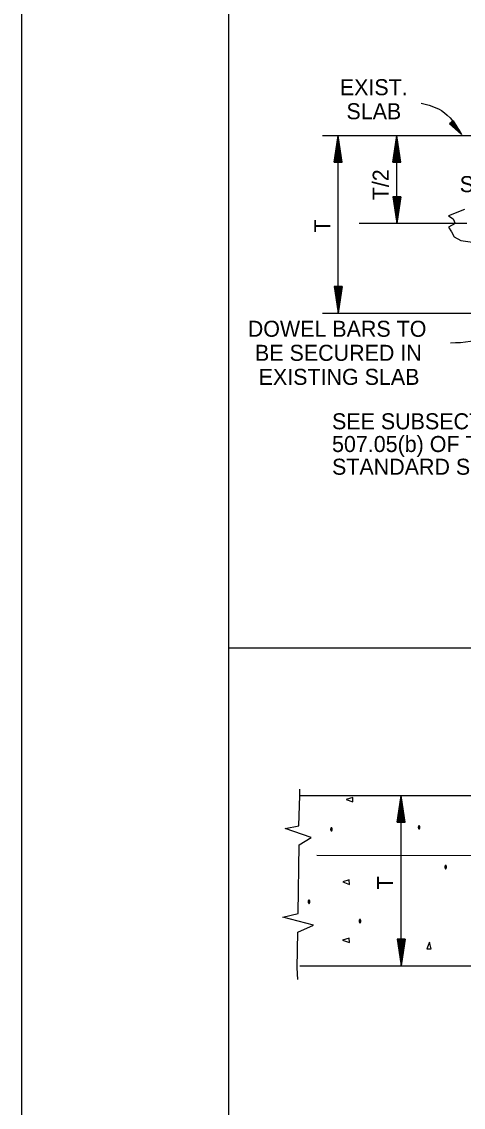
# Model space of a CAD drawing. Extents: x 1375738 to 1375905, y 380661 to 380875.
# Drawn here: x 1375738.22 to 1375751.44, y 380817.52 to 380850.01 of the extents above; entities that cross this region are included whole.
import ezdxf

# ---------------------------------------------------------------- set-up
doc = ezdxf.new("R2010")
doc.units = 0
for name, color, linetype in [('R_Border', 7, 'Continuous'), ('R_Draft', 7, 'Continuous'), ('R_No Plot', 7, 'Continuous')]:
    doc.layers.add(name, color=color, linetype=linetype)

msp = doc.modelspace()

# ---------------------------------------------------------------- linework, layer by layer
at = {"layer": 'R_Border'}
for p, q in [((1375744.419, 380770.053), (1375744.419, 380872.783)), ((1375744.419, 380831.274), (1375786.095, 380831.274))]:
    msp.add_line(p, q, dxfattribs=at)
at = {"layer": 'R_Draft'}
for p, q in [((1375751.135, 380847.052), (1375751.025, 380846.96)), ((1375751.025, 380846.96), (1375751.39, 380846.64)), ((1375751.034, 380846.967), (1375751.338, 380846.701)), ((1375751.043, 380846.975), (1375751.285, 380846.764)), ((1375751.053, 380846.983), (1375751.233, 380846.825)), ((1375751.062, 380846.991), (1375751.181, 380846.887)), ((1375751.071, 380846.999), (1375751.129, 380846.948)), ((1375751.088, 380847.013), (1375751.129, 380846.948)), ((1375751.097, 380847.021), (1375751.181, 380846.887)), ((1375751.107, 380847.029), (1375751.233, 380846.825)), ((1375751.116, 380847.037), (1375751.285, 380846.764)), ((1375751.125, 380847.045), (1375751.338, 380846.701)), ((1375751.135, 380847.052), (1375751.39, 380846.64)), ((1375747.225, 380846.607), (1375756.842, 380846.602)), ((1375747.574, 380845.806), (1375747.694, 380846.606)), ((1375747.594, 380845.806), (1375747.694, 380846.472)), ((1375747.694, 380841.293), (1375747.694, 380846.606)), ((1375747.814, 380845.806), (1375747.694, 380846.606)), ((1375747.794, 380845.806), (1375747.694, 380846.472)), ((1375749.326, 380845.806), (1375749.446, 380846.606)), ((1375749.346, 380845.806), (1375749.446, 380846.472)), ((1375749.446, 380843.972), (1375749.446, 380846.606)), ((1375749.566, 380845.806), (1375749.446, 380846.606)), ((1375749.546, 380845.806), (1375749.446, 380846.472)), ((1375747.615, 380845.806), (1375747.694, 380846.335)), ((1375747.635, 380845.806), (1375747.694, 380846.202)), ((1375747.774, 380845.806), (1375747.694, 380846.335)), ((1375747.754, 380845.806), (1375747.694, 380846.202)), ((1375749.367, 380845.806), (1375749.446, 380846.335)), ((1375749.387, 380845.806), (1375749.446, 380846.202)), ((1375749.526, 380845.806), (1375749.446, 380846.335)), ((1375749.506, 380845.806), (1375749.446, 380846.202)), ((1375747.655, 380845.806), (1375747.694, 380846.066)), ((1375747.675, 380845.806), (1375747.694, 380845.932)), ((1375747.733, 380845.806), (1375747.694, 380846.066)), ((1375747.713, 380845.806), (1375747.694, 380845.932)), ((1375749.407, 380845.806), (1375749.446, 380846.066)), ((1375749.427, 380845.806), (1375749.446, 380845.932)), ((1375749.485, 380845.806), (1375749.446, 380846.066)), ((1375749.465, 380845.806), (1375749.446, 380845.932)), ((1375747.574, 380845.806), (1375747.814, 380845.806)), ((1375749.326, 380845.806), (1375749.566, 380845.806)), ((1375749.326, 380844.772), (1375749.446, 380843.972)), ((1375749.566, 380844.772), (1375749.326, 380844.772)), ((1375749.346, 380844.772), (1375749.446, 380844.105)), ((1375749.367, 380844.772), (1375749.446, 380844.243)), ((1375749.387, 380844.772), (1375749.446, 380844.376)), ((1375749.407, 380844.772), (1375749.446, 380844.512)), ((1375749.427, 380844.772), (1375749.446, 380844.645)), ((1375749.566, 380844.772), (1375749.446, 380843.972)), ((1375749.485, 380844.772), (1375749.446, 380844.512)), ((1375749.526, 380844.772), (1375749.446, 380844.243)), ((1375749.546, 380844.772), (1375749.446, 380844.105)), ((1375749.506, 380844.772), (1375749.446, 380844.376)), ((1375749.465, 380844.772), (1375749.446, 380844.645)), ((1375751.547, 380843.972), (1375748.317, 380843.972)), ((1375747.574, 380842.093), (1375747.694, 380841.293)), ((1375747.814, 380842.093), (1375747.574, 380842.093)), ((1375747.594, 380842.093), (1375747.694, 380841.427)), ((1375747.615, 380842.093), (1375747.694, 380841.564)), ((1375747.635, 380842.093), (1375747.694, 380841.698)), ((1375747.655, 380842.093), (1375747.694, 380841.833)), ((1375747.675, 380842.093), (1375747.694, 380841.967)), ((1375747.814, 380842.093), (1375747.694, 380841.293)), ((1375747.733, 380842.093), (1375747.694, 380841.833)), ((1375747.774, 380842.093), (1375747.694, 380841.564)), ((1375747.794, 380842.093), (1375747.694, 380841.427)), ((1375747.754, 380842.093), (1375747.694, 380841.698)), ((1375747.713, 380842.093), (1375747.694, 380841.967)), ((1375747.222, 380841.294), (1375756.839, 380841.288)), ((1375746.547, 380826.851), (1375746.54, 380827.039)), ((1375746.513, 380825.946), (1375746.547, 380826.851)), ((1375746.547, 380826.851), (1375770.735, 380826.837)), ((1375749.459, 380826.049), (1375749.58, 380826.849)), ((1375749.479, 380826.049), (1375749.58, 380826.716)), ((1375749.577, 380821.754), (1375749.58, 380826.849)), ((1375749.699, 380826.049), (1375749.58, 380826.849)), ((1375749.679, 380826.049), (1375749.58, 380826.716)), ((1375749.5, 380826.049), (1375749.58, 380826.578)), ((1375749.52, 380826.049), (1375749.579, 380826.445)), ((1375749.639, 380826.049), (1375749.579, 380826.445)), ((1375749.659, 380826.049), (1375749.58, 380826.578)), ((1375749.459, 380826.049), (1375749.699, 380826.049)), ((1375749.54, 380826.049), (1375749.579, 380826.309)), ((1375749.56, 380826.049), (1375749.579, 380826.176)), ((1375749.618, 380826.049), (1375749.579, 380826.309)), ((1375749.598, 380826.049), (1375749.579, 380826.176)), ((1375746.108, 380825.859), (1375746.513, 380825.946)), ((1375746.882, 380825.597), (1375746.108, 380825.859)), ((1375746.497, 380823.319), (1375746.52, 380825.371)), ((1375746.52, 380825.371), (1375746.882, 380825.597)), ((1375747.053, 380825.061), (1375770.11, 380825.048)), ((1375746.033, 380823.213), (1375746.497, 380823.319)), ((1375746.954, 380822.966), (1375746.033, 380823.213)), ((1375746.465, 380821.693), (1375746.485, 380822.756)), ((1375746.485, 380822.756), (1375746.954, 380822.966)), ((1375749.457, 380822.554), (1375749.577, 380821.754)), ((1375749.697, 380822.554), (1375749.457, 380822.554)), ((1375749.477, 380822.554), (1375749.577, 380821.888)), ((1375749.498, 380822.554), (1375749.577, 380822.025)), ((1375749.518, 380822.554), (1375749.577, 380822.159)), ((1375749.538, 380822.554), (1375749.577, 380822.294)), ((1375749.558, 380822.554), (1375749.577, 380822.428)), ((1375749.697, 380822.554), (1375749.577, 380821.754)), ((1375749.616, 380822.554), (1375749.577, 380822.294)), ((1375749.657, 380822.554), (1375749.577, 380822.025)), ((1375749.677, 380822.554), (1375749.577, 380821.888)), ((1375749.637, 380822.554), (1375749.577, 380822.159)), ((1375749.596, 380822.554), (1375749.577, 380822.428)), ((1375746.482, 380821.343), (1375746.465, 380821.693)), ((1375746.544, 380821.756), (1375770.732, 380821.742))]:
    msp.add_line(p, q, dxfattribs=at)
for points in [[(1375751.479, 380844.398), (1375750.999, 380844.201), (1375751.141, 380844.116), (1375751.197, 380843.975), (1375750.999, 380843.862), (1375751.084, 380843.72), (1375751.169, 380843.579), (1375751.366, 380843.466), (1375751.79, 380843.41)], [(1375747.934, 380826.735), (1375748.134, 380826.663), (1375748.128, 380826.795), (1375747.934, 380826.735)], [(1375747.828, 380824.262), (1375748.027, 380824.19), (1375748.022, 380824.322), (1375747.828, 380824.262)], [(1375747.827, 380822.522), (1375748.027, 380822.449), (1375748.021, 380822.582), (1375747.827, 380822.522)], [(1375750.423, 380822.459), (1375750.35, 380822.259), (1375750.482, 380822.265), (1375750.423, 380822.459)]]:
    msp.add_lwpolyline(points, dxfattribs=at)
for points in [[(1375750.175, 380847.578), (1375750.783, 380847.357), (1375751.39, 380846.64)], [(1375751.059, 380840.4), (1375752.163, 380840.621), (1375752.881, 380841.946), (1375753.157, 380843.713)], [(1375747.466, 380825.839), (1375747.468, 380825.856), (1375747.475, 380825.877), (1375747.485, 380825.887), (1375747.491, 380825.889), (1375747.502, 380825.883), (1375747.507, 380825.877), (1375747.512, 380825.865), (1375747.516, 380825.847), (1375747.516, 380825.839), (1375747.515, 380825.825), (1375747.512, 380825.811), (1375747.507, 380825.8), (1375747.498, 380825.79), (1375747.491, 380825.789), (1375747.482, 380825.792), (1375747.475, 380825.8), (1375747.472, 380825.808), (1375747.468, 380825.82), (1375747.466, 380825.827), (1375747.466, 380825.839)], [(1375750.092, 380825.9), (1375750.094, 380825.917), (1375750.101, 380825.938), (1375750.111, 380825.948), (1375750.117, 380825.95), (1375750.128, 380825.944), (1375750.133, 380825.938), (1375750.138, 380825.926), (1375750.142, 380825.909), (1375750.142, 380825.9), (1375750.141, 380825.887), (1375750.138, 380825.872), (1375750.133, 380825.861), (1375750.124, 380825.851), (1375750.117, 380825.85), (1375750.108, 380825.853), (1375750.101, 380825.861), (1375750.098, 380825.869), (1375750.094, 380825.881), (1375750.092, 380825.889), (1375750.092, 380825.9)], [(1375750.886, 380824.709), (1375750.888, 380824.727), (1375750.895, 380824.747), (1375750.905, 380824.757), (1375750.911, 380824.759), (1375750.922, 380824.753), (1375750.927, 380824.747), (1375750.932, 380824.735), (1375750.936, 380824.718), (1375750.936, 380824.709), (1375750.935, 380824.696), (1375750.932, 380824.681), (1375750.927, 380824.671), (1375750.918, 380824.661), (1375750.911, 380824.659), (1375750.902, 380824.662), (1375750.895, 380824.67), (1375750.892, 380824.678), (1375750.888, 380824.69), (1375750.886, 380824.698), (1375750.886, 380824.709)], [(1375746.794, 380823.671), (1375746.796, 380823.689), (1375746.804, 380823.709), (1375746.814, 380823.719), (1375746.82, 380823.721), (1375746.83, 380823.715), (1375746.835, 380823.709), (1375746.841, 380823.697), (1375746.844, 380823.68), (1375746.844, 380823.671), (1375746.843, 380823.658), (1375746.841, 380823.643), (1375746.836, 380823.633), (1375746.826, 380823.623), (1375746.82, 380823.621), (1375746.81, 380823.624), (1375746.804, 380823.632), (1375746.8, 380823.64), (1375746.796, 380823.652), (1375746.795, 380823.66), (1375746.794, 380823.671)], [(1375748.321, 380823.091), (1375748.323, 380823.109), (1375748.33, 380823.129), (1375748.34, 380823.139), (1375748.346, 380823.141), (1375748.357, 380823.135), (1375748.362, 380823.129), (1375748.368, 380823.117), (1375748.371, 380823.1), (1375748.371, 380823.091), (1375748.37, 380823.078), (1375748.368, 380823.063), (1375748.362, 380823.053), (1375748.353, 380823.043), (1375748.346, 380823.041), (1375748.337, 380823.044), (1375748.33, 380823.052), (1375748.327, 380823.06), (1375748.323, 380823.072), (1375748.322, 380823.08), (1375748.321, 380823.091)]]:
    msp.add_spline(points, degree=3, dxfattribs=at)
at = {"layer": 'R_No Plot'}
for points in [[(1375738.215, 380874.73), (1375904.885, 380874.73), (1375904.885, 380768.061), (1375738.215, 380768.061)], [(1375861.379, 380872.783), (1375871.189, 380872.783), (1375871.189, 380867.843), (1375879.245, 380867.843), (1375890.845, 380867.843), (1375890.845, 380851.508), (1375902.449, 380851.508), (1375902.509, 380770.053), (1375744.419, 380770.053), (1375744.419, 380872.783)]]:
    msp.add_lwpolyline(points, close=True, dxfattribs=at)

# ---------------------------------------------------------------- texts
at = {"layer": 'R_Draft'}
for s, p in [('EXIST.', (1375747.742, 380847.814)), ('SLAB', (1375747.941, 380847.094)), ('SAWED FACE', (1375751.332, 380844.913)), ('DOWEL BARS TO', (1375744.986, 380840.583)), ('BE SECURED IN', (1375745.202, 380839.863)), ('EXISTING SLAB', (1375745.311, 380839.143)), ('SEE SUBSECTION', (1375747.509, 380837.813)), ('507.05(b) OF THE', (1375747.509, 380837.133)), ('STANDARD SPECIFICATIONS', (1375747.509, 380836.453))]:
    msp.add_text(s, height=0.48, dxfattribs=at).set_placement(p)
for s, rotation, p in [('T/2', 90, (1375749.206, 380844.669)), ('T', 90, (1375747.454, 380843.705)), ('T', 89.9685, (1375749.338, 380824.039))]:
    msp.add_text(s, height=0.48, rotation=rotation, dxfattribs=at).set_placement(p)

doc.saveas('drawing.dxf')
